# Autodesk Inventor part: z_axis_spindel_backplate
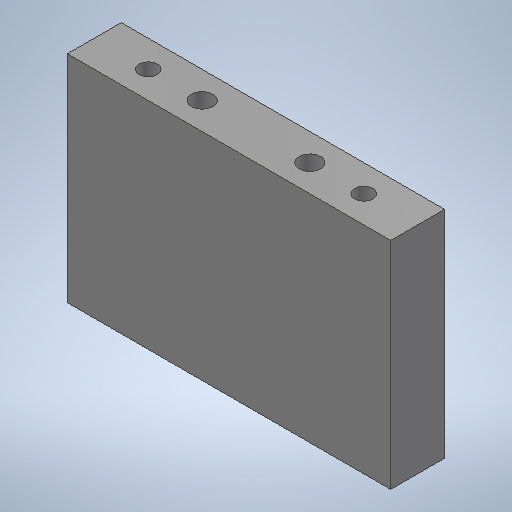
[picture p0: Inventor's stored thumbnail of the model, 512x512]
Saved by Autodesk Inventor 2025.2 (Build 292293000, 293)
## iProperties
Created: 2025-04
Part Number: z_axis_spindel_backplate
Material: 1.0037 S235JR
Document SubType Name: Modeling
Designer: BennF
Density: 7.85 g/cm^3
Appearance: Stahl
Author: BennF
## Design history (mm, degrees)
sketch "Sketch2"
  geometry: L1 (-30, 20)-(30, 20); L2 (30, 20)-(30, -20); L3 (30, -20)-(-30, -20); L4 (-30, -20)-(-30, 20); 3 further points
  constraints: 8 end point, 2 midpoint, 2 parallel, 1 horizontal, 1 horizontal alignment, 1 perpendicular, 1 vertical alignment
  dimensions: "d0" = 60 distance of L1.start L1.end; "d1" = 40 distance of L1.end L2.end
extrude "Extrusion1" new body sketch "Sketch2" distance "d2" = 10; taper "d3" = 0 deg
sketch "Sketch3"
  geometry: L1 (10, 5)-(50, 5); L2 (0, 0)-(60, 0) reference; L3 (60, 0)-(60, 10) reference; 4 further points
  constraints: 3 midpoint, 2 end point, 2 horizontal alignment, 1 horizontal, 1 vertical alignment
  dimensions: "d11" = 40 distance of L1.start L1.end
hole "Hole1" sketch "Sketch3" at (10, 5), (50, 5) diameter "d4" = 3.4; stored, may be unused: countersink angle "d8" = 90 deg, drill point angle "d10" = 0 deg; dims "d5" = 8, "d6" = 9.4, "d7" = 2, "d9" = 15
sketch "Sketch4"
  geometry: C1 r 1.7 at (10, 5) reference; C2 r 1.7 at (50, 5) reference; 3 further points
  constraints: 2 coincident
hole "Hole2" sketch "Sketch4" at (50, 5), (10, 5) diameter "d12" = 3.4; stored, may be unused: countersink angle "d16" = 90 deg, drill point angle "d18" = 0 deg; dims "d13" = 8, "d14" = 10, "d15" = 2, "d17" = 15
sketch "Sketch5"
  geometry: L1 (20, 5)-(40, 5); L2 (0, 0)-(60, 0) reference; C1 r 1.7 at (50, 5) reference; 3 further points
  constraints: 2 end point, 2 horizontal alignment, 2 midpoint, 1 horizontal, 1 vertical alignment
  dimensions: "d26" = 20 distance of L1.start L1.end
hole "Hole3" sketch "Sketch5" at (20, 5), (40, 5) diameter "d19" = 4; stored, may be unused: countersink angle "d23" = 90 deg, drill point angle "d25" = 118 deg; dims "d20" = 8, "d21" = 4, "d22" = 2, "d24" = 11.8
body "Solid1"
